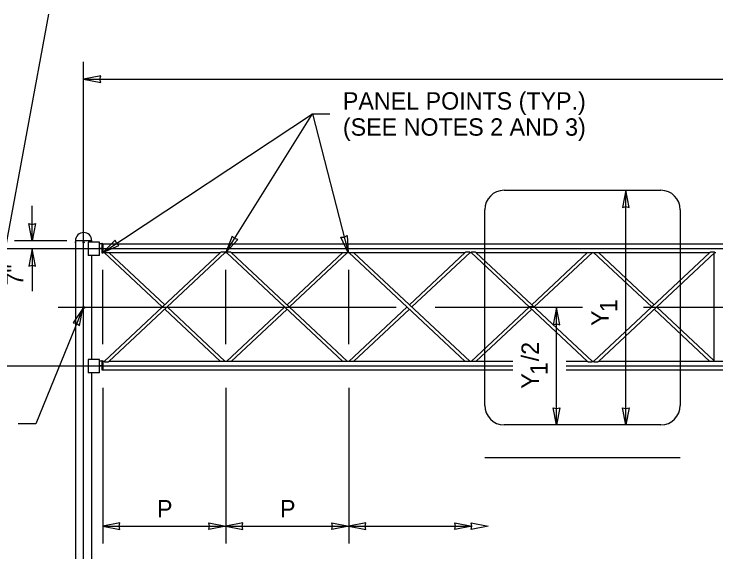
# Model space of a CAD drawing. Extents: x 99862 to 104211, y 98939 to 111076.
# Drawn here: x 100720 to 101366, y 101176 to 101671 of the extents above; entities that cross this region are included whole.
import ezdxf

# ---------------------------------------------------------------- set-up
doc = ezdxf.new("R2010")
doc.units = 0
for name, color, linetype in [('Level 15', 7, 'Continuous'), ('Level 2', 7, 'Continuous'), ('Level 20', 7, 'Continuous'), ('Level 3', 7, 'Continuous'), ('Level 4', 7, 'Continuous'), ('Level 5', 7, 'Continuous'), ('Level 6', 7, 'Continuous'), ('Level 7', 7, 'Continuous'), ('Level 9', 7, 'Continuous')]:
    doc.layers.add(name, color=color, linetype=linetype)

msp = doc.modelspace()

# ---------------------------------------------------------------- linework, layer by layer
at = {"layer": 'Level 15'}
for p, q in [((100711.86, 101454.49), (100751.8, 101670.74)), ((100783.8, 100893.86), (100783.8, 101626.74)), ((100783.8, 101610.74), (102621.87, 101610.74)), ((100801.52, 101451.3), (100994.34, 101578.74)), ((100914.68, 101451.3), (100994.34, 101578.74)), ((100994.34, 101578.74), (101010.34, 101578.74)), ((100994.34, 101578.74), (101027.27, 101451.3)), ((101282.8, 101292.49), (101282.8, 101508.49)), ((100736.3, 101462.08), (100736.3, 101494.08)), ((100768.3, 101462.08), (100720.3, 101462.08)), ((101702.84, 101454.49), (100680.3, 101454.49)), ((100736.3, 101454.49), (100736.3, 101415.56)), ((100801.52, 101366.8), (100801.52, 101435.3)), ((100914.68, 101366.8), (100914.68, 101435.3)), ((101027.84, 101366.8), (101027.84, 101435.3)), ((100783.19, 101399.78), (100739.67, 101293.49)), ((101071.3, 101400.49), (100760.3, 101400.49)), ((101242.8, 101400.49), (101107.3, 101400.49)), ((101218.8, 101292.49), (101218.8, 101400.49)), ((101710.7, 101400.49), (101298.8, 101400.49)), ((101178.8, 101346.49), (100680.3, 101346.49)), ((102074.87, 101346.49), (101227.67, 101346.49)), ((100801.52, 101326.74), (100801.52, 101183.3)), ((100914.68, 101326.74), (100914.68, 101183.3)), ((101027.84, 101326.74), (101027.84, 101183.3)), ((100739.67, 101293.49), (100723.67, 101293.49)), ((100801.52, 101199.3), (100914.68, 101199.3)), ((100914.68, 101199.3), (101027.84, 101199.3)), ((101027.84, 101199.3), (101140.99, 101199.3))]:
    msp.add_line(p, q, dxfattribs=at)
for points in [[(100783.8, 101610.74), (100799.53, 101607.66), (100798.8, 101610.74), (100799.53, 101613.82)], [(101282.8, 101508.49), (101279.72, 101492.76), (101282.8, 101493.49), (101285.89, 101492.76)], [(100736.3, 101462.08), (100733.22, 101477.81), (100736.3, 101477.08), (100739.39, 101477.81)], [(100914.68, 101451.3), (100925.6, 101463.03), (100922.6, 101464.04), (100920.36, 101466.28)], [(101027.1, 101450.9), (101020.32, 101465.42), (101023.49, 101465.45), (101026.31, 101466.9)], [(100801.52, 101451.3), (100816.29, 101457.53), (100813.96, 101459.68), (100812.85, 101462.64)], [(100736.3, 101454.49), (100733.22, 101438.76), (100736.3, 101439.49), (100739.39, 101438.76)], [(100783.19, 101399.78), (100774.31, 101386.44), (100777.44, 101385.93), (100780, 101384.08)], [(101218.8, 101400.49), (101215.72, 101384.76), (101218.8, 101385.49), (101221.89, 101384.76)], [(101218.8, 101292.49), (101215.72, 101308.21), (101218.8, 101307.49), (101221.89, 101308.21)], [(101282.8, 101292.49), (101279.72, 101308.21), (101282.8, 101307.49), (101285.89, 101308.21)], [(100801.52, 101199.3), (100817.25, 101196.22), (100816.52, 101199.3), (100817.25, 101202.39)], [(100914.68, 101199.3), (100898.95, 101196.22), (100899.68, 101199.3), (100898.95, 101202.39)], [(100914.68, 101199.3), (100930.4, 101196.22), (100929.68, 101199.3), (100930.4, 101202.39)], [(101027.84, 101199.3), (101012.11, 101196.22), (101012.84, 101199.3), (101012.11, 101202.39)], [(101027.84, 101199.3), (101043.56, 101196.22), (101042.83, 101199.3), (101043.56, 101202.39)], [(101140.99, 101199.3), (101125.27, 101196.22), (101125.99, 101199.3), (101125.27, 101202.39)], [(101155.99, 101199.3), (101140.26, 101196.22), (101140.99, 101199.3), (101140.26, 101202.39)]]:
    msp.add_lwpolyline(points, close=True, dxfattribs=at)
at = {"layer": 'Level 2'}
for p, q in [((101170.8, 101508.49), (101314.8, 101508.49)), ((101152.8, 101310.49), (101152.8, 101490.49)), ((101332.8, 101490.49), (101332.8, 101310.49)), ((101314.8, 101292.49), (101170.8, 101292.49)), ((101152.8, 101262.49), (101332.8, 101262.49))]:
    msp.add_line(p, q, dxfattribs=at)
for centre, start, end in [((101170.8, 101490.49), 90, 180), ((101314.8, 101490.49), 0, 90), ((101170.8, 101310.49), 180, 270), ((101314.8, 101310.49), 270, 0)]:
    msp.add_arc(centre, 18, start, end, dxfattribs=at)
at = {"layer": 'Level 3'}
for p, q in [((100776.3, 101462.08), (100776.3, 101460.94)), ((100776.3, 101460.3), (100776.3, 101002.33)), ((100791.3, 101461.07), (100791.3, 101462.08)), ((100791.3, 101352.58), (100791.3, 101448.4)), ((100802.65, 101451.3), (100856.19, 101401.05)), ((100858.38, 101403.11), (100807.03, 101451.3)), ((101022.33, 101451.3), (100970.98, 101403.11)), ((100973.17, 101401.05), (101026.71, 101451.3)), ((101027.84, 101451.3), (101134.92, 101350.8)), ((101139.3, 101350.8), (101032.22, 101451.3)), ((101247.51, 101451.3), (101196.16, 101403.11)), ((101198.36, 101401.05), (101251.9, 101451.3)), ((101253.02, 101451.3), (101306.57, 101401.05)), ((101308.76, 101403.11), (101257.41, 101451.3)), ((100914.12, 101350.8), (100860.57, 101401.05)), ((100968.78, 101401.05), (100915.24, 101350.8)), ((101193.97, 101401.05), (101140.43, 101350.8)), ((101363.55, 101351.68), (101310.95, 101401.05)), ((100858.38, 101399), (100909.73, 101350.8)), ((100919.63, 101350.8), (100970.98, 101399)), ((101144.81, 101350.8), (101196.16, 101399)), ((101308.76, 101399), (101360.11, 101350.8)), ((100914.12, 101350.8), (100914.12, 101350.8)), ((100915.24, 101350.8), (100915.24, 101350.8)), ((101139.3, 101350.8), (101139.3, 101350.8)), ((101140.43, 101350.8), (101140.43, 101350.8)), ((101364.49, 101350.8), (101364.49, 101350.8)), ((100791.3, 101002.33), (100791.3, 101340.4))]:
    msp.add_line(p, q, dxfattribs=at)
msp.add_circle((100783.8, 101400.49), 0.938, dxfattribs=at)
for points in [[(100776.31, 101460.38), (100776.31, 101460.39), (100776.31, 101460.41), (100776.31, 101460.43), (100776.31, 101460.46), (100776.31, 101460.49), (100776.31, 101460.52), (100776.31, 101460.55), (100776.31, 101460.58), (100776.31, 101460.62), (100776.31, 101460.65), (100776.31, 101460.68), (100776.31, 101460.71), (100776.31, 101460.73), (100776.31, 101460.76), (100776.31, 101460.78), (100776.31, 101460.79), (100776.31, 101460.8), (100776.31, 101460.8)], [(100791.3, 101460.8), (100791.3, 101460.79), (100791.3, 101460.77), (100791.3, 101460.76), (100791.3, 101460.73), (100791.3, 101460.7), (100791.3, 101460.67), (100791.3, 101460.65), (100791.3, 101460.61), (100791.3, 101460.58)]]:
    msp.add_open_spline(points, degree=3, dxfattribs=at)
at = {"layer": 'Level 4'}
for p, q in [((100798.24, 101459.36), (100800.4, 101459.36)), ((100800.87, 101459.36), (100800.4, 101459.36)), ((100800.87, 101459.36), (100801.52, 101459.36)), ((100800.87, 101450.74), (100800.87, 101459.36)), ((100801.52, 101459.36), (100801.52, 101450.74)), ((100798.24, 101455.33), (100800.49, 101455.33)), ((100800.49, 101454.77), (100798.24, 101454.77)), ((102604.15, 101458.8), (100801.52, 101458.8)), ((100801.52, 101450.74), (100800.87, 101450.74)), ((100801.52, 101451.3), (100909.73, 101451.3)), ((100909.73, 101451.3), (100802.65, 101350.8)), ((100807.03, 101350.8), (100914.12, 101451.3)), ((100914.12, 101451.3), (100915.24, 101451.3)), ((100915.24, 101451.3), (101022.33, 101350.8)), ((100919.63, 101451.3), (101134.92, 101451.3)), ((101026.71, 101350.8), (100919.63, 101451.3)), ((101134.92, 101451.3), (101083.57, 101403.11)), ((101085.76, 101401.05), (101139.3, 101451.3)), ((101139.3, 101451.3), (101140.43, 101451.3)), ((101140.43, 101451.3), (101247.52, 101350.8)), ((101144.78, 101451.3), (101360.12, 101451.3)), ((101251.9, 101350.8), (101144.81, 101451.3)), ((101360.11, 101451.3), (101253.02, 101350.8)), ((101257.41, 101350.8), (101364.49, 101451.3)), ((101364.49, 101451.3), (101365.62, 101451.3)), ((101081.38, 101401.05), (101027.84, 101350.8)), ((101198.36, 101401.05), (101193.97, 101401.05)), ((101032.22, 101350.8), (101083.57, 101399)), ((100798.24, 101351.36), (100800.4, 101351.36)), ((100800.87, 101351.36), (100800.4, 101351.36)), ((100800.87, 101342.74), (100800.87, 101351.36)), ((100800.87, 101351.36), (100801.52, 101351.36)), ((100801.52, 101351.36), (100801.52, 101342.74)), ((100802.65, 101350.8), (100801.52, 101350.8)), ((100802.65, 101350.8), (100802.65, 101350.8)), ((101178.8, 101350.8), (100807.03, 101350.8)), ((101247.51, 101350.8), (101227.67, 101350.8)), ((101253.02, 101350.8), (101251.9, 101350.8)), ((101251.9, 101350.8), (101251.9, 101350.8)), ((101253.02, 101350.8), (101253.02, 101350.8)), ((101472.7, 101350.8), (101257.41, 101350.8)), ((100798.24, 101347.33), (100800.49, 101347.33)), ((100800.49, 101346.77), (100798.24, 101346.77)), ((100801.52, 101342.74), (100800.87, 101342.74)), ((100801.52, 101343.3), (101178.8, 101343.3)), ((101227.67, 101343.3), (102074.87, 101343.3))]:
    msp.add_line(p, q, dxfattribs=at)
for centre, start, end in [((100800.49, 101455.71), 270, 0), ((100800.49, 101454.4), 0, 90), ((100800.49, 101347.71), 270, 0), ((100800.49, 101346.4), 0, 90)]:
    msp.add_arc(centre, 0.375, start, end, dxfattribs=at)
for points in [[(100914.12, 101451.3), (100914.11, 101451.3), (100914.09, 101451.31), (100914.03, 101451.33), (100913.98, 101451.35), (100913.91, 101451.38), (100913.82, 101451.41), (100913.72, 101451.43), (100913.6, 101451.47), (100913.48, 101451.49), (100913.34, 101451.52), (100913.19, 101451.55), (100913.03, 101451.57), (100912.78, 101451.6), (100912.52, 101451.62), (100912.26, 101451.62), (100911.89, 101451.62), (100911.51, 101451.59), (100911.16, 101451.54), (100910.86, 101451.51), (100910.57, 101451.46), (100910.32, 101451.42), (100910.2, 101451.4), (100910.09, 101451.37), (100910, 101451.36), (100909.92, 101451.34), (100909.85, 101451.33), (100909.8, 101451.32), (100909.76, 101451.31), (100909.74, 101451.3), (100909.73, 101451.3), (100909.73, 101451.3), (100909.73, 101451.3), (100909.73, 101451.3)], [(100919.63, 101451.3), (100919.63, 101451.3), (100919.61, 101451.3), (100919.59, 101451.31), (100919.57, 101451.31), (100919.53, 101451.32), (100919.49, 101451.33), (100919.41, 101451.35), (100919.3, 101451.37), (100919.19, 101451.39), (100918.99, 101451.43), (100918.76, 101451.47), (100918.52, 101451.5), (100918.15, 101451.56), (100917.75, 101451.6), (100917.35, 101451.61), (100917.08, 101451.62), (100916.8, 101451.61), (100916.53, 101451.59), (100916.34, 101451.57), (100916.14, 101451.55), (100915.97, 101451.51), (100915.82, 101451.48), (100915.69, 101451.45), (100915.58, 101451.42), (100915.47, 101451.39), (100915.38, 101451.35), (100915.33, 101451.33), (100915.27, 101451.31), (100915.24, 101451.3), (100915.24, 101451.3)], [(101139.3, 101451.3), (101139.3, 101451.3), (101139.27, 101451.31), (101139.22, 101451.33), (101139.17, 101451.35), (101139.1, 101451.38), (101139, 101451.41), (101138.91, 101451.43), (101138.79, 101451.47), (101138.67, 101451.49), (101138.53, 101451.52), (101138.38, 101451.55), (101138.22, 101451.57), (101137.97, 101451.6), (101137.71, 101451.62), (101137.45, 101451.62), (101137.08, 101451.62), (101136.7, 101451.59), (101136.34, 101451.54), (101136.05, 101451.51), (101135.76, 101451.46), (101135.51, 101451.42), (101135.39, 101451.4), (101135.28, 101451.37), (101135.18, 101451.36), (101135.1, 101451.34), (101135.03, 101451.33), (101134.99, 101451.32), (101134.95, 101451.31), (101134.93, 101451.3), (101134.92, 101451.3), (101134.92, 101451.3), (101134.92, 101451.3), (101134.92, 101451.3)], [(101144.81, 101451.3), (101144.81, 101451.3), (101144.8, 101451.3), (101144.78, 101451.31), (101144.76, 101451.31), (101144.72, 101451.32), (101144.67, 101451.33), (101144.6, 101451.35), (101144.49, 101451.37), (101144.38, 101451.39), (101144.18, 101451.43), (101143.95, 101451.47), (101143.7, 101451.5), (101143.34, 101451.56), (101142.94, 101451.6), (101142.53, 101451.61), (101142.26, 101451.62), (101141.99, 101451.61), (101141.72, 101451.59), (101141.52, 101451.57), (101141.33, 101451.55), (101141.15, 101451.51), (101141.01, 101451.48), (101140.88, 101451.45), (101140.77, 101451.42), (101140.66, 101451.39), (101140.57, 101451.35), (101140.51, 101451.33), (101140.46, 101451.31), (101140.43, 101451.3), (101140.43, 101451.3)], [(101364.49, 101451.3), (101364.49, 101451.3), (101364.46, 101451.31), (101364.41, 101451.33), (101364.36, 101451.35), (101364.28, 101451.38), (101364.19, 101451.41), (101364.1, 101451.43), (101363.98, 101451.47), (101363.85, 101451.49), (101363.72, 101451.52), (101363.56, 101451.55), (101363.4, 101451.57), (101363.16, 101451.6), (101362.9, 101451.62), (101362.64, 101451.62), (101362.26, 101451.62), (101361.89, 101451.59), (101361.53, 101451.54), (101361.23, 101451.51), (101360.95, 101451.46), (101360.69, 101451.42), (101360.58, 101451.4), (101360.47, 101451.37), (101360.37, 101451.36), (101360.29, 101451.34), (101360.22, 101451.33), (101360.17, 101451.32), (101360.14, 101451.31), (101360.12, 101451.3), (101360.11, 101451.3), (101360.11, 101451.3), (101360.11, 101451.3), (101360.11, 101451.3)], [(100802.65, 101350.8), (100802.65, 101350.8), (100802.67, 101350.79), (100802.71, 101350.78), (100802.76, 101350.76), (100802.82, 101350.74), (100802.91, 101350.71), (100803, 101350.68), (100803.11, 101350.65), (100803.23, 101350.62), (100803.36, 101350.59), (100803.51, 101350.57), (100803.67, 101350.54), (100803.9, 101350.51), (100804.15, 101350.49), (100804.39, 101350.49), (100804.43, 101350.49), (100804.47, 101350.49), (100804.51, 101350.49), (100804.88, 101350.49), (100805.26, 101350.52), (100805.61, 101350.56), (100805.91, 101350.6), (100806.19, 101350.64), (100806.45, 101350.69), (100806.56, 101350.71), (100806.67, 101350.73), (100806.77, 101350.75), (100806.85, 101350.76), (100806.92, 101350.78), (100806.97, 101350.79), (100807, 101350.8), (100807.02, 101350.8), (100807.03, 101350.8), (100807.03, 101350.8), (100807.03, 101350.8), (100807.03, 101350.8)], [(101247.51, 101350.8), (101247.51, 101350.8), (101247.52, 101350.8), (101247.52, 101350.8), (101247.53, 101350.8), (101247.55, 101350.79), (101247.59, 101350.79), (101247.64, 101350.78), (101247.71, 101350.76), (101247.8, 101350.74), (101247.94, 101350.72), (101248.11, 101350.69), (101248.28, 101350.66), (101248.59, 101350.6), (101248.94, 101350.55), (101249.29, 101350.52), (101249.54, 101350.5), (101249.79, 101350.49), (101250.04, 101350.49), (101250.29, 101350.49), (101250.55, 101350.5), (101250.79, 101350.53), (101250.97, 101350.55), (101251.14, 101350.58), (101251.29, 101350.62), (101251.45, 101350.65), (101251.58, 101350.69), (101251.68, 101350.72), (101251.77, 101350.75), (101251.83, 101350.78), (101251.87, 101350.79), (101251.89, 101350.8), (101251.9, 101350.8), (101251.9, 101350.8)], [(101253.02, 101350.8), (101253.02, 101350.8), (101253.04, 101350.79), (101253.09, 101350.78), (101253.13, 101350.76), (101253.2, 101350.74), (101253.29, 101350.71), (101253.37, 101350.68), (101253.49, 101350.65), (101253.61, 101350.62), (101253.74, 101350.59), (101253.89, 101350.57), (101254.04, 101350.54), (101254.27, 101350.51), (101254.52, 101350.49), (101254.77, 101350.49), (101254.81, 101350.49), (101254.84, 101350.49), (101254.88, 101350.49), (101255.25, 101350.49), (101255.63, 101350.52), (101255.99, 101350.56), (101256.28, 101350.6), (101256.57, 101350.64), (101256.82, 101350.69), (101256.94, 101350.71), (101257.05, 101350.73), (101257.14, 101350.75), (101257.22, 101350.76), (101257.29, 101350.78), (101257.34, 101350.79), (101257.38, 101350.8), (101257.4, 101350.8), (101257.4, 101350.8), (101257.41, 101350.8), (101257.41, 101350.8), (101257.41, 101350.8)]]:
    msp.add_open_spline(points, degree=3, dxfattribs=at)
at = {"layer": 'Level 5'}
msp.add_line((100791.3, 101462.08), (100776.3, 101462.08), dxfattribs=at)
msp.add_arc((100783.8, 101462.08), 7.5, 0, 180, dxfattribs=at)
at = {"layer": 'Level 6'}
for p, q in [((100798.24, 101460.58), (100788.04, 101460.58)), ((100788.04, 101460.58), (100788.04, 101448.4)), ((100798.24, 101448.4), (100798.24, 101460.58)), ((100798.24, 101448.4), (100788.04, 101448.4)), ((100788.04, 101352.58), (100788.04, 101340.4)), ((100798.24, 101352.58), (100788.04, 101352.58)), ((100798.24, 101340.4), (100798.24, 101352.58)), ((100798.24, 101340.4), (100788.04, 101340.4))]:
    msp.add_line(p, q, dxfattribs=at)
at = {"layer": 'Level 7'}
msp.add_line((101363.55, 101450.42), (101363.55, 101350.8), dxfattribs=at)
at = {"layer": 'Level 9'}
for p, q in [((100775.97, 101461.07), (100775.93, 101461.01)), ((100775.93, 101461.01), (100775.93, 101460.95)), ((100775.93, 101460.95), (100775.93, 101460.94)), ((100775.93, 101460.94), (100775.93, 101460.59)), ((100775.93, 101460.59), (100775.93, 101460.57)), ((100775.93, 101460.57), (100775.93, 101460.22)), ((100775.93, 101460.22), (100775.93, 101460.16)), ((100775.93, 101460.22), (100775.93, 101460.22)), ((100775.93, 101460.16), (100775.97, 101460.1)), ((100775.97, 101461.07), (100776.3, 101461.07)), ((100775.97, 101460.83), (100776.31, 101460.83)), ((100775.97, 101460.34), (100776.31, 101460.34)), ((100775.97, 101460.1), (100776.3, 101460.1)), ((100776.31, 101461.07), (100776.31, 101460.83)), ((100776.31, 101460.83), (100776.31, 101460.34)), ((100776.31, 101460.34), (100776.31, 101460.1)), ((100783.59, 101460.94), (100783.6, 101460.95)), ((100784, 101460.95), (100784.02, 101460.94)), ((100784.02, 101460.22), (100784.01, 101460.22)), ((100784.23, 101460.59), (100784.23, 101460.57)), ((100791.3, 101460.83), (100791.3, 101461.07)), ((100791.64, 101461.07), (100791.3, 101461.07)), ((100791.3, 101460.58), (100791.3, 101460.83)), ((100791.64, 101460.83), (100791.3, 101460.83)), ((100791.68, 101461.01), (100791.64, 101461.07)), ((100791.68, 101461.01), (100791.68, 101460.95)), ((100791.68, 101460.94), (100791.68, 101460.95)), ((100791.68, 101460.94), (100791.68, 101460.58))]:
    msp.add_line(p, q, dxfattribs=at)
for start, end in [(121.1969, 180), (180, 299.24462), (61.56083, 118.8031), (1.41676, 58.43917), (300.75799, 358.58324)]:
    msp.add_arc((100783.8, 101460.58), 0.422, start, end, dxfattribs=at)
for points, degree in [([(100775.97, 101461.07), (100775.95, 101461.03), (100775.93, 101460.99), (100775.93, 101460.95)], 2), ([(100775.93, 101460.94), (100775.93, 101460.94), (100775.93, 101460.94), (100775.93, 101460.94), (100775.93, 101460.9), (100775.95, 101460.86), (100775.97, 101460.83)], 3), ([(100775.97, 101460.83), (100775.95, 101460.75), (100775.93, 101460.67), (100775.93, 101460.59)], 2), ([(100775.93, 101460.57), (100775.93, 101460.49), (100775.95, 101460.42), (100775.97, 101460.34)], 2), ([(100775.97, 101460.34), (100775.95, 101460.3), (100775.93, 101460.26), (100775.93, 101460.22)], 2), ([(100775.93, 101460.22), (100775.93, 101460.21), (100775.93, 101460.21), (100775.93, 101460.21), (100775.93, 101460.17), (100775.95, 101460.13), (100775.97, 101460.1)], 3), ([(100775.94, 101460.98), (100775.94, 101461.01), (100775.95, 101461.04), (100775.97, 101461.07)], 2), ([(100775.97, 101460.1), (100775.96, 101460.12), (100775.95, 101460.14), (100775.94, 101460.16)], 2), ([(100783.38, 101460.83), (100783.45, 101460.87), (100783.52, 101460.9), (100783.59, 101460.94)], 2), ([(100783.38, 101460.83), (100783.38, 101460.75), (100783.38, 101460.67), (100783.38, 101460.58)], 2), ([(100783.38, 101460.58), (100783.38, 101460.5), (100783.38, 101460.42), (100783.38, 101460.34)], 2), ([(100783.8, 101460.1), (100783.73, 101460.14), (100783.65, 101460.18), (100783.58, 101460.23), (100783.51, 101460.26), (100783.45, 101460.3), (100783.38, 101460.34)], 3), ([(100783.6, 101460.95), (100783.6, 101460.95), (100783.61, 101460.96), (100783.61, 101460.96), (100783.67, 101461), (100783.74, 101461.03), (100783.8, 101461.07)], 3), ([(100783.8, 101461.07), (100783.87, 101461.03), (100783.94, 101460.99), (100784, 101460.95)], 2), ([(100784.01, 101460.22), (100784.01, 101460.21), (100784, 101460.21), (100784, 101460.21), (100783.93, 101460.17), (100783.87, 101460.13), (100783.8, 101460.1)], 3), ([(100784.02, 101460.94), (100784.03, 101460.94), (100784.03, 101460.94), (100784.03, 101460.94), (100784.1, 101460.9), (100784.16, 101460.86), (100784.23, 101460.83)], 3), ([(100784.23, 101460.34), (100784.16, 101460.3), (100784.09, 101460.26), (100784.02, 101460.22)], 2), ([(100784.23, 101460.83), (100784.23, 101460.75), (100784.23, 101460.67), (100784.23, 101460.59)], 2), ([(100784.23, 101460.57), (100784.23, 101460.49), (100784.23, 101460.42), (100784.23, 101460.34)], 2), ([(100791.64, 101461.07), (100791.65, 101461.05), (100791.66, 101461.02), (100791.67, 101461)], 2), ([(100791.68, 101460.95), (100791.68, 101460.95), (100791.68, 101460.96), (100791.68, 101460.96), (100791.67, 101461), (100791.66, 101461.03), (100791.64, 101461.07)], 3), ([(100791.64, 101460.83), (100791.66, 101460.87), (100791.68, 101460.9), (100791.68, 101460.94)], 2), ([(100791.64, 101460.83), (100791.66, 101460.75), (100791.68, 101460.67), (100791.68, 101460.58)], 2)]:
    msp.add_open_spline(points, degree=degree, dxfattribs=at)

# ---------------------------------------------------------------- texts
at = {"layer": 'Level 15'}
for p in [(100851.31, 101207.3), (100964.47, 101207.3)]:
    msp.add_text('P', height=16, dxfattribs=at).set_placement(p)
at = {"layer": 'Level 20'}
for s, p in [('PANEL POINTS (TYP.)', (101022.34, 101582.74)), ('(SEE NOTES 2 AND 3)', (101022.34, 101558.74))]:
    msp.add_text(s, height=16, dxfattribs=at).set_placement(p)
for s, rotation, p in [('7"', 90, (100728.3, 101420.76)), ('1', 90.00001, (101274.8, 101396.26)), ('Y', 90.00001, (101266.8, 101383.6)), ('/2', 90.00001, (101202.67, 101351.04)), ('1', 90.00001, (101210.67, 101338.47)), ('Y', 90.00001, (101202.67, 101325.8))]:
    msp.add_text(s, height=16, rotation=rotation, dxfattribs=at).set_placement(p)

doc.saveas('drawing.dxf')
